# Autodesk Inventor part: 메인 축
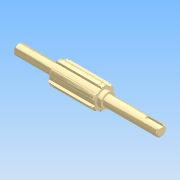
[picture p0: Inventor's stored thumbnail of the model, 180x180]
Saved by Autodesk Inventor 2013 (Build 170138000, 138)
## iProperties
Company: 한국ATC센터
Created: 2014-07
Part Number: 메인 축
Document SubType Name: 모델링
Designer: KYOUNG IL JANG
Mass: 168.566 g
Surface Area: 72.5104 cm^2
Volume: 21.4461 cm^3
Density: 7.86 g/cm^3
Material: 강철, 연강
변환 표준: STEP AP214IS
파일 이름: C:\Users\SeoGD\Desktop\?쒗뿕\硫붿씤 異?.stp
전처리기: Build: 253, Release: 2010 SP1 - Date: Wed 07/29/2009
전송 단위: 밀리미터
불확실성: 0.01
Author: KYOUNG IL JANG
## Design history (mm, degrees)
sketch "스케치1"
  geometry: L1 (-69.5, 0)-(69.5, 0); L2 (69.5, 0)-(69.5, 5); L3 (69.5, 5)-(55.5, 5); L4 (55.5, 5)-(55.5, 4.8); L5 (55.5, 4.8)-(54.35, 4.8); L6 (54.35, 4.8)-(54.35, 5); L7 (54.35, 5)-(30.5, 5); L8 (30.5, 5)-(30.5, 9); L9 (30.5, 9)-(-13.5, 9); L10 (-13.5, 9)-(-13.5, 7); L11 (-13.5, 7)-(-17.5, 7); L12 (-17.5, 7)-(-17.5, 5); L13 (-17.5, 5)-(-69.5, 5); L14 (-69.5, 5)-(-69.5, 0); 2 further points
  constraints: 28 end point, 9 parallel, 4 collinear, 2 perpendicular, 1 coincident, 1 horizontal, 1 midpoint
  dimensions: "d2" = 1.15 distance between parallel lines of L6 L4; "d3" = 10 diameter of L3 L1; "d4" = 9.6 diameter of L5 L1; "d6" = 44 distance between parallel lines of L10 L8; "d7" = 4 distance between parallel lines of L12 L10; "d8" = 14 diameter of L11 L1; "d9" = 18 diameter of L9 L1; "d33" = 52 distance from line of L12.end L14; "d37" = 39 distance between parallel lines of L8 L2; "d38" = 14 distance between parallel lines of L2 L4
revolve "회전1" sketch "스케치1" stored, may be unused: angle "d10" = 90 deg
sketch "스케치2"
  geometry: L1 (2.5, 10.712)-(2.5, 8.646); L2 (-2.5, 10.712)-(-2.5, 8.646); A1 r 9 centre (0, 0) between (2.5, 8.646) and (-2.5, 8.646) reference; A2 r 11 centre (0, 0) between (2.5, 10.712) and (-2.5, 10.712); 1 further point
  constraints: 4 end point, 4 point on circle, 2 parallel, 1 centre point, 1 coincident, 1 vertical
  dimensions: "d11" = 22 diameter of A2; "d12" = 5 distance between parallel lines of L1 L2
extrude "돌출1" join sketch "스케치2" stored distance "d13" = 10; taper "d14" = 0 deg
chamfer "모따기1" distance "d15" = 1; stored, may be unused: second distance "d16" = 2, angle "d17" = 45 deg
node "작업 평면1"
node "작업 평면2"
sketch "스케치3"
  geometry: L1 (2.5, 10.712)-(2.5, 10.198); L2 (-2.5, 10.712)-(-2.5, 10.198); A1 r 11 centre (0, 0) between (2.5, 10.712) and (-2.5, 10.712) reference; A2 r 10.5 centre (0, 0) between (2.5, 10.198) and (-2.5, 10.198); 1 further point
  constraints: 4 end point, 2 point on circle, 1 centre point, 1 coincident, 1 parallel, 1 vertical
  dimensions: "d19" = 21 diameter of A2
extrude "돌출2" cut sketch "스케치3" distance "d20" = 1.35; taper "d21" = 0 deg
node "작업 평면3"
sketch "스케치4"
  geometry: L1 (-26, -5)-(-26, 5) reference; L2 (-26, 1.5)-(-12.5, 1.5); L3 (-12.5, -1.5)-(-26, -1.5); A1 r 1.5 centre (-12.5, 0) between (-12.5, -1.5) and (-12.5, 1.5); 2 further points
  constraints: 4 end point, 2 perpendicular, 2 point on circle, 2 point on line, 2 tangent, 1 centre point, 1 horizontal alignment, 1 midpoint
  dimensions: "d25" = 3 distance between parallel lines of L3 L2; "d26" = 15 dimension on A1 L1
extrude "돌출3" cut sketch "스케치4" distance "d27" = 1.8; taper "d28" = 0 deg
chamfer "모따기2" distance "d29" = 1; stored, may be unused: second distance "d30" = 2, angle "d31" = 45 deg
node "솔리드1"
node "솔리드 본체"
node "곡면 본체"
mirror "대칭1"
pattern_circular "원형 패턴1" dims "d23" = 360 deg
node "솔리드2"
other parameters: "d18" = -1.65
